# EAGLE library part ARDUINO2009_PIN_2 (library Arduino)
The Arduino Duemilanove ("2009") is a microcontroller board based on the ATmega168 or ATmega328. - 14 digital input/output pins (of which 6 can be used as PWM outputs) - 6 analog inputs, a 16 MHz crystal oscillator - USB connection - power jack - ISP header - reset button It contains everything needed to support the microcontroller; simply connect it to a computer with a USB cable or power it with a AC-to-DC adapter or battery to get started http://arduino.cc/en/Main/ArduinoBoardDuemilanove
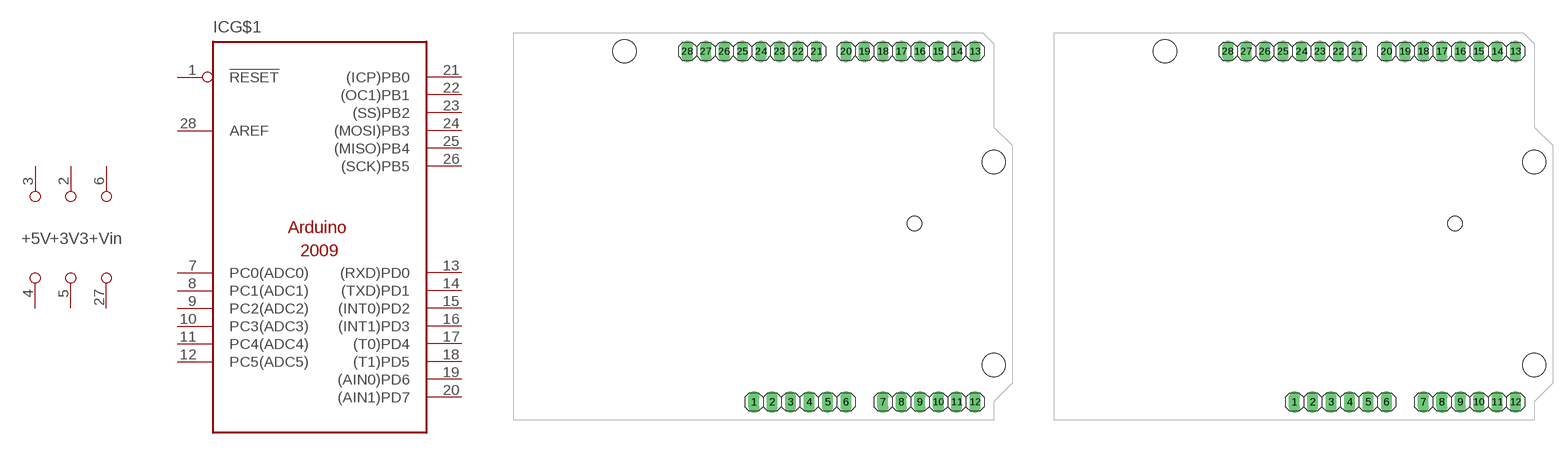
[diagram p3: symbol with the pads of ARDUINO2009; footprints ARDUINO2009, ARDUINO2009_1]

Designator prefix IC; gates G$1=ARDUINO2009_PIN_1 G$2=PWR5V G$3=PWR3V3 G$4=PWRVIN

## ARDUINO2009_PIN_20  [ARDUINO2009]
1  G$1:!RESET
2  G$3:+3V3  pwr
3  G$2:+5V  pwr
4  G$2:GND  pwr
5  G$3:GND  pwr
6  G$4:+VIN  pwr
7  G$1:PC0(ADC0)
8  G$1:PC1(ADC1)
9  G$1:PC2(ADC2)
10  G$1:PC3(ADC3)
11  G$1:PC4(ADC4)
12  G$1:PC5(ADC5)
13  G$1:(RXD)PD0
14  G$1:(TXD)PD1
15  G$1:(INT0)PD2
16  G$1:(INT1)PD3
17  G$1:(T0)PD4
18  G$1:(T1)PD5
19  G$1:(AIN0)PD6
20  G$1:(AIN1)PD7
21  G$1:(ICP)PB0
22  G$1:(OC1)PB1
23  G$1:(SS)PB2
24  G$1:(MOSI)PB3
25  G$1:(MISO)PB4
26  G$1:(SCK)PB5
27  G$4:GND  pwr
28  G$1:AREF

## ARDUINO2009_PIN_21  [ARDUINO2009_1]
Pads as for ARDUINO2009

## ARDUINO2009_PIN_22  [ARDUINO2009_2]
Pads as for ARDUINO2009

## Footprint ARDUINO2009 (pad centres in mm)
drill 1.016 long: 1 33.02,2.54; 2 35.56,2.54; 3 38.1,2.54; 4 40.64,2.54; 5 43.18,2.54; 6 45.72,2.54; 7 50.8,2.54; 8 53.34,2.54; 9 55.88,2.54; 10 58.42,2.54; 11 60.96,2.54; 12 63.5,2.54; 13 63.5,50.8; 14 60.96,50.8; 15 58.42,50.8; 16 55.88,50.8; 17 53.34,50.8; 18 50.8,50.8; 19 48.26,50.8; 20 45.72,50.8; 21 41.656,50.8; 22 39.116,50.8; 23 36.576,50.8; 24 34.036,50.8; 25 31.496,50.8; 26 28.956,50.8; 27 26.416,50.8; 28 23.876,50.8
hole 3.2 at 15.24,50.8
hole 3.2 at 66.04,35.56
hole 3.2 at 66.04,7.62
hole 2 at 55.17,27.114

## Footprint ARDUINO2009_1 (pad centres in mm)
drill 1.016 long: 1 33.02,2.54; 2 35.56,2.54; 3 38.1,2.54; 4 40.64,2.54; 5 43.18,2.54; 6 45.72,2.54; 7 50.8,2.54; 8 53.34,2.54; 9 55.88,2.54; 10 58.42,2.54; 11 60.96,2.54; 12 63.5,2.54; 13 63.5,50.8; 14 60.96,50.8; 15 58.42,50.8; 16 55.88,50.8; 17 53.34,50.8; 18 50.8,50.8; 19 48.26,50.8; 20 45.72,50.8; 21 41.656,50.8; 22 39.116,50.8; 23 36.576,50.8; 24 34.036,50.8; 25 31.496,50.8; 26 28.956,50.8; 27 26.416,50.8; 28 23.876,50.8
hole 3.2 at 15.24,50.8
hole 3.2 at 66.04,35.56
hole 3.2 at 66.04,7.62
hole 2 at 55.17,27.114

## Footprint ARDUINO2009_2 (pad centres in mm)
drill 1.016 long: 1 33.02,2.54; 2 35.56,2.54; 3 38.1,2.54; 4 40.64,2.54; 5 43.18,2.54; 6 45.72,2.54; 7 50.8,2.54; 8 53.34,2.54; 9 55.88,2.54; 10 58.42,2.54; 11 60.96,2.54; 12 63.5,2.54; 13 63.5,50.8; 14 60.96,50.8; 15 58.42,50.8; 16 55.88,50.8; 17 53.34,50.8; 18 50.8,50.8; 19 48.26,50.8; 20 45.72,50.8; 21 41.656,50.8; 22 39.116,50.8; 23 36.576,50.8; 24 34.036,50.8; 25 31.496,50.8; 26 28.956,50.8; 27 26.416,50.8; 28 23.876,50.8
hole 3.2 at 15.24,50.8
hole 3.2 at 66.04,35.56
hole 3.2 at 66.04,7.62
